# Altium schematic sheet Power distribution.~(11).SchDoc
size A3; SheetNumber: 7; SheetTotal: 8
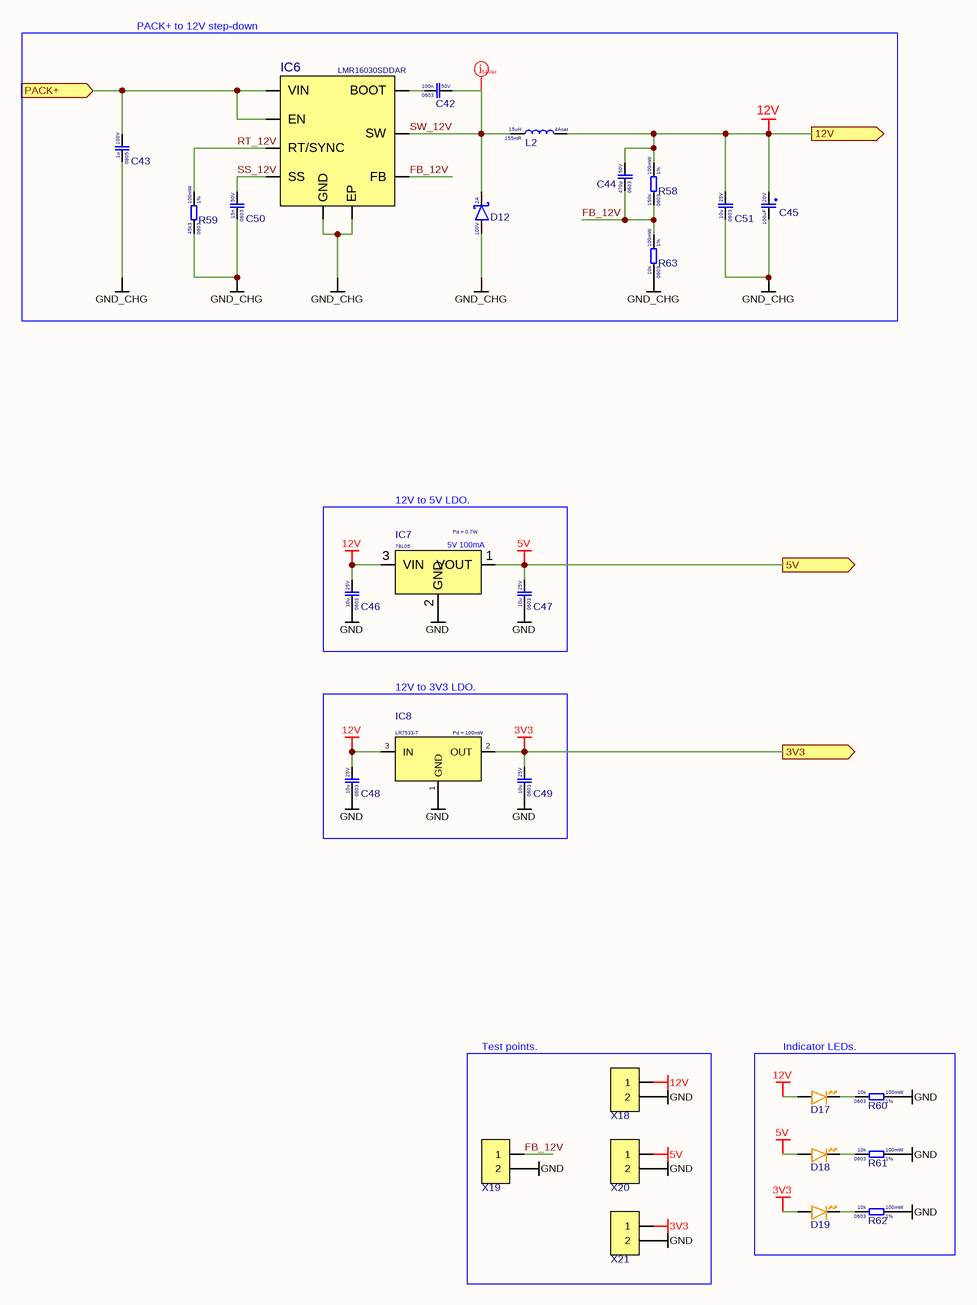
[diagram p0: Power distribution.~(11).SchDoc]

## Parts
C42  Voltage Rating: 50V  Case Code (Imperial): 0603  Capacitance: 100n  [CAP 0603]  (hidden comment: CC0603KRX7R9BB104)
C43  Voltage Rating: 100V  Case Code (Imperial): 0805  Capacitance: 1u  [Cap_0805]  (hidden comment: CC0805KKX7R0BB105)
C44  Voltage Rating: 50V  Case Code (Imperial): 0603  Capacitance: 470p  [CAP 0603]  (hidden comment: 0603B471K500NT)
C45  Voltage Rating: 20V  Capacitance: 100uF  [CASE D 7343-31]  (hidden comment: TAJD107K020RNJ)
C46  Voltage Rating: 25V  Case Code (Imperial): 0603  Capacitance: 10u  [CAP 0603]  (hidden comment: CL10A106MA8NRNC)
C47  Voltage Rating: 25V  Case Code (Imperial): 0603  Capacitance: 10u  [CAP 0603]  (hidden comment: CL10A106MA8NRNC)
C48  Voltage Rating: 25V  Case Code (Imperial): 0603  Capacitance: 10u  [CAP 0603]  (hidden comment: CL10A106MA8NRNC)
C49  Voltage Rating: 25V  Case Code (Imperial): 0603  Capacitance: 10u  [CAP 0603]  (hidden comment: CL10A106MA8NRNC)
C50  Voltage Rating: 50V  Case Code (Imperial): 0603  Capacitance: 15n  [CAP 0603]  (hidden comment: CC0603KRX7R9BB153)
C51  Voltage Rating: 25V  Case Code (Imperial): 0603  Capacitance: 10u  [CAP 0603]  (hidden comment: CL10A106MA8NRNC)
D12  Forward Current: 2A  Reverse Voltage: 100V  [SMAF]  (hidden comment: SS210F)
D17  XL-1608UOC-06  [DIODE_0603_ORANGE]  (value not drawn)
D18  XL-1608UOC-06  [DIODE_0603_ORANGE]  (value not drawn)
D19  XL-1608UOC-06  [DIODE_0603_ORANGE]  (value not drawn)
IC6  LMR16030SDDAR  [SOIC8-EP]
IC7  Pd = 0.7W  [SOT-89-3]
IC8  Pd = 100mW  [SOT-23 123]
L2  Resistance: 155mR  Saturation current: 4Asat  Inductance: 15uH  [FXL0630-150-M]  (hidden comment: FXL0630-150-M)
R58  Resistance Tolerance: 1%  Resistance: 150k  Power Rating: 100mW  Case Code (Imperial): 0603  [RES_0603]  (hidden comment: 0603WAF1503T5E)
R59  Resistance Tolerance: 1%  Resistance: 45k3  Power Rating: 100mW  Case Code (Imperial): 0603  [RES_0603]  (hidden comment: 0603WAF4532T5E)
R60  Resistance Tolerance: 1%  Resistance: 10k  Power Rating: 100mW  Case Code (Imperial): 0603  [RES_0603]  (hidden comment: 0603WAF1002T5E)
R61  Resistance Tolerance: 1%  Resistance: 10k  Power Rating: 100mW  Case Code (Imperial): 0603  [RES_0603]  (hidden comment: 0603WAF1002T5E)
R62  Resistance Tolerance: 1%  Resistance: 10k  Power Rating: 100mW  Case Code (Imperial): 0603  [RES_0603]  (hidden comment: 0603WAF1002T5E)
R63  Resistance Tolerance: 1%  Resistance: 10k  Power Rating: 100mW  Case Code (Imperial): 0603  [RES_0603]  (hidden comment: 0603WAF1002T5E)
X18  ZX-PZ1.27-1-2PZZ  [Pin header 1x2 1.27mmP THT Vertical]  (value not drawn)
X19  ZX-PZ1.27-1-2PZZ  [Pin header 1x2 1.27mmP THT Vertical]  (value not drawn)
X20  ZX-PZ1.27-1-2PZZ  [Pin header 1x2 1.27mmP THT Vertical]  (value not drawn)
X21  ZX-PZ1.27-1-2PZZ  [Pin header 1x2 1.27mmP THT Vertical]  (value not drawn)

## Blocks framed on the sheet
PACK+ to 12V step-down: C42-C45 C50 C51 D12 IC6 L2 R58 R59 R63
12V to 5V LDO.: C46 C47 IC7
12V to 3V3 LDO.: C48 C49 IC8
Test points.: X18-X21
Indicator LEDs.: D17-D19 R60-R62

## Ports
3V3 (out, see CHARGER[4C], USB PD[5B]), 5V (out, see CHARGER[4C], USB PD[2B]), 12V (out, see CHARGER[4C], Charger BQ25756[8A]), PACK+ (in, see CHARGER[3C], BMS[8A], Charger BQ25756[1A], CHARGER[1B])

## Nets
3V3: C49.2 D19.A IC8.2(OUT) X21.1 ; port 3V3
5V: C47.2 D18.A IC7.1(VOUT) X20.1 ; port 5V
12V: C44.2 C45.+ C46.2 C48.2 C51.2 D17.A IC7.3(VIN) IC8.3(IN) L2.2 R58.2 X18.1 ; port 12V
GND: C46.1 C47.1 C48.1 C49.1 IC7.2(GND) IC8.1(GND) R60.2 R61.2 R62.2 X18.2 X19.2 X20.2 X21.2
GND_CHG: C43.1 C45.- C50.1 C51.1 D12.A IC6.7(GND) IC6.9(EP) R59.1 R63.1
FB_12V: C44.1 IC6.5(FB) R58.1 R63.2 X19.1
PACK+: C43.2 IC6.2(VIN) IC6.3(EN) ; port PACK+
RT_12V: IC6.4(RT/SYNC) R59.2
SS_12V: C50.2 IC6.6(SS)
SW_12V: C42.2 D12.K IC6.8(SW) L2.1
NetC42_1: C42.1 IC6.1(BOOT)
NetD17_K: D17.K R60.1
NetD18_K: D18.K R61.1
NetD19_K: D19.K R62.1

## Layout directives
net class 54Vac: SW_12V

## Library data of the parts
C42 = CC0603KRX7R9BB104: Cap 100nF 50V 0603 X7R; Manufacturer: Yageo
C43 = CC0805KKX7R0BB105: Cap 1uF 100V 0805 X7R; Manufacturer: Yageo
C44 = 0603B471K500NT: Cap 470pF 50V 0603 X7R; Manufacturer: FH
C45 = TAJD107K020RNJ: Tantal cap 100uF 20V 500mR CASE D-7343-31; Manufacturer: Kyocera AVX
C46-C49 C51 = CL10A106MA8NRNC: Cap 10uF 25V 0603 X5R; Manufacturer: Samsung
C50 = CC0603KRX7R9BB153: Cap 15nF 50V 0603 X7R; Manufacturer: Yageo; Manufacturer Part Number: CC0603KRX7R9BB104
D12 = SS210F: Schottky 100V 2A 850mVf SMAF; Manufacturer: GOODWORK
D17-D19 = XL-1608UOC-06: LED Orange 0603 20mA; Manufacturer: XINGLIGHT
IC6 = LMR16030SDDAR: Step-down 4.3~60Vin 3A SOIC8-EP 0.2~2.5MHz IntFET; Manufacturer: Texas Instruments
IC7 = 78L05: LDO 5V 100mA 30Vin; Manufacturer: UMW
IC8 = LR7533-T: LDO 24Vin 3.3Vout fixed; Manufacturer: LR
L2 = FXL0630-150-M: Inductor 15uH 3A 115mR 30V; Manufacturer: Cjiang
R58 = 0603WAF1503T5E: Res 150k 0603 1% 100mW 75V; Manufacturer: Uni-Royal
R59 = 0603WAF4532T5E: Res 45k3 0603 1% 100mW 75V; Manufacturer: Uni-Royal
R60-R63 = 0603WAF1002T5E: Res 10k 0603 1% 100mW 75V; Manufacturer: Uni-Royal
X18-X21 = ZX-PZ1.27-1-2PZZ: Pin header 1x2 1.27mmP THT Vertical; Manufacturer: Megastar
